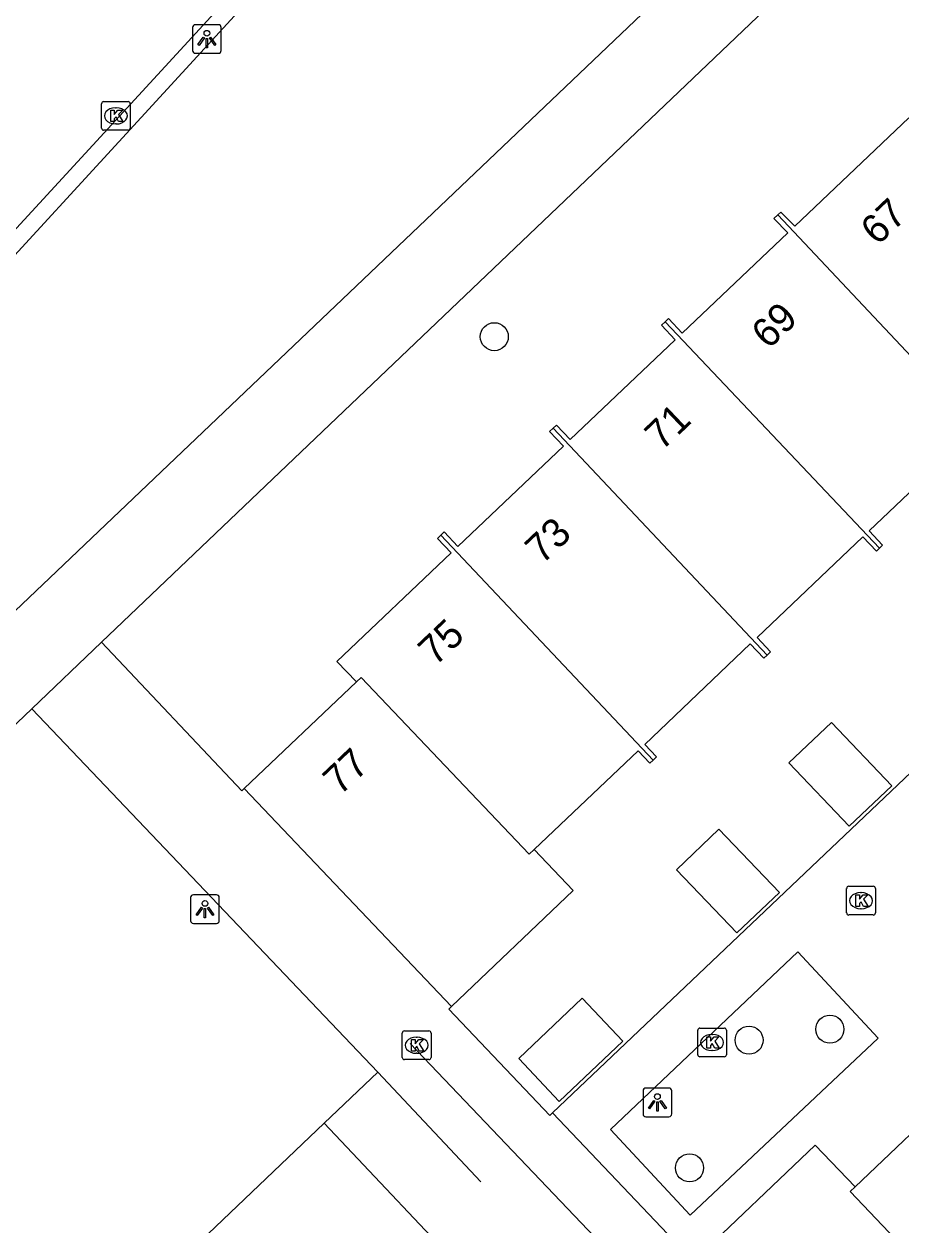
# Model space of a CAD drawing. Extents: x 162532 to 163264, y 381233 to 382042.
# Drawn here: x 163000.28 to 163030.86, y 381418.45 to 381460.32 of the extents above; entities that cross this region are included whole.
import ezdxf

# ---------------------------------------------------------------- set-up
doc = ezdxf.new("R2010")
doc.units = 0
for name, color, linetype in [('IMGEO_Boom', 7, 'Continuous'), ('IMGEO_Kolk', 7, 'Continuous'), ('IMGEO_Lichtpunt', 7, 'Continuous'), ('IMGEO_Muur', 7, 'Continuous'), ('IMGEO_Pand', 7, 'Continuous'), ('IMGEO_Pand_nummerreeks', 7, 'Continuous'), ('IMGEO_Rijbaan_lokaal_open', 7, 'Continuous'), ('IMGEO_Voetpad_gesloten', 7, 'Continuous'), ('IMGEO_Voetpad_open', 7, 'Continuous')]:
    doc.layers.add(name, color=color, linetype=linetype)

msp = doc.modelspace()

# ---------------------------------------------------------------- linework, layer by layer
at = {"layer": 'IMGEO_Boom'}
for centre in [(163016.681, 381449.417), (163028.386, 381425.275), (163025.567, 381424.892), (163023.491, 381420.44)]:
    msp.add_circle(centre, 0.489, dxfattribs=at)
at = {"layer": 'IMGEO_Kolk'}
for p, q in [((163002.984, 381456.688), (163002.984, 381457.54)), ((163003.059, 381457.614), (163003.911, 381457.614)), ((163003.985, 381457.54), (163003.985, 381456.688)), ((163003.472, 381457.394), (163003.497, 381457.394)), ((163003.495, 381456.834), (163003.47, 381456.834)), ((163003.911, 381456.614), (163003.059, 381456.614)), ((163029.045, 381430.256), (163029.897, 381430.256)), ((163028.97, 381429.33), (163028.97, 381430.182)), ((163029.458, 381430.036), (163029.483, 381430.036)), ((163029.971, 381430.182), (163029.971, 381429.33)), ((163029.481, 381429.476), (163029.456, 381429.476)), ((163029.897, 381429.256), (163029.045, 381429.256)), ((163013.549, 381425.214), (163014.401, 381425.214)), ((163023.777, 381424.386), (163023.777, 381425.238)), ((163023.852, 381425.312), (163024.704, 381425.312)), ((163024.778, 381425.238), (163024.778, 381424.386)), ((163013.474, 381424.288), (163013.474, 381425.14)), ((163013.962, 381424.994), (163013.987, 381424.994)), ((163014.475, 381425.14), (163014.475, 381424.288)), ((163024.265, 381425.092), (163024.29, 381425.092)), ((163013.985, 381424.434), (163013.96, 381424.434)), ((163024.288, 381424.532), (163024.263, 381424.532)), ((163014.401, 381424.214), (163013.549, 381424.214)), ((163024.704, 381424.312), (163023.852, 381424.312))]:
    msp.add_line(p, q, dxfattribs=at)
for points in [[(163002.984, 381456.688), (163002.984, 381457.54)], [(163003.059, 381457.614), (163003.911, 381457.614)], [(163003.985, 381457.54), (163003.985, 381456.688)], [(163003.305, 381457.314), (163003.428, 381457.314), (163003.428, 381457.163), (163003.558, 381457.314), (163003.722, 381457.314), (163003.576, 381457.163), (163003.729, 381456.914), (163003.577, 381456.914), (163003.492, 381457.078), (163003.428, 381457.011), (163003.428, 381456.914), (163003.305, 381456.914), (163003.305, 381457.314)], [(163003.911, 381456.614), (163003.059, 381456.614)], [(163029.045, 381430.256), (163029.897, 381430.256)], [(163028.97, 381429.33), (163028.97, 381430.182)], [(163029.291, 381429.956), (163029.414, 381429.956), (163029.414, 381429.805), (163029.544, 381429.956), (163029.708, 381429.956), (163029.562, 381429.805), (163029.715, 381429.556), (163029.563, 381429.556), (163029.478, 381429.72), (163029.414, 381429.653), (163029.414, 381429.556), (163029.291, 381429.556), (163029.291, 381429.956)], [(163029.971, 381430.182), (163029.971, 381429.33)], [(163029.897, 381429.256), (163029.045, 381429.256)], [(163013.549, 381425.214), (163014.401, 381425.214)], [(163023.777, 381424.386), (163023.777, 381425.238)], [(163023.852, 381425.312), (163024.704, 381425.312)], [(163024.778, 381425.238), (163024.778, 381424.386)], [(163013.474, 381424.288), (163013.474, 381425.14)], [(163013.795, 381424.914), (163013.918, 381424.914), (163013.918, 381424.763), (163014.048, 381424.914), (163014.212, 381424.914), (163014.066, 381424.763), (163014.219, 381424.514), (163014.067, 381424.514), (163013.982, 381424.678), (163013.918, 381424.611), (163013.918, 381424.514), (163013.795, 381424.514), (163013.795, 381424.914)], [(163014.475, 381425.14), (163014.475, 381424.288)], [(163024.098, 381425.012), (163024.221, 381425.012), (163024.221, 381424.861), (163024.351, 381425.012), (163024.515, 381425.012), (163024.369, 381424.861), (163024.522, 381424.612), (163024.37, 381424.612), (163024.285, 381424.776), (163024.221, 381424.709), (163024.221, 381424.612), (163024.098, 381424.612), (163024.098, 381425.012)], [(163014.401, 381424.214), (163013.549, 381424.214)], [(163024.704, 381424.312), (163023.852, 381424.312)]]:
    msp.add_lwpolyline(points, dxfattribs=at)
for centre, start, end in [((163003.061, 381457.538), 91.552, 178.448), ((163003.061, 381457.538), 91.552, 178.448), ((163003.909, 381457.538), 1.552, 88.448), ((163003.909, 381457.538), 1.552, 88.448), ((163003.061, 381456.69), 181.552, 268.448), ((163003.061, 381456.69), 181.552, 268.448), ((163003.909, 381456.69), 271.552, 358.448), ((163003.909, 381456.69), 271.552, 358.448), ((163029.047, 381430.18), 91.552, 178.448), ((163029.047, 381430.18), 91.552, 178.448), ((163029.895, 381430.18), 1.552, 88.448), ((163029.895, 381430.18), 1.552, 88.448), ((163029.047, 381429.332), 181.552, 268.448), ((163029.047, 381429.332), 181.552, 268.448), ((163029.895, 381429.332), 271.552, 358.448), ((163029.895, 381429.332), 271.552, 358.448), ((163013.551, 381425.138), 91.552, 178.448), ((163013.551, 381425.138), 91.552, 178.448), ((163014.399, 381425.138), 1.552, 88.448), ((163014.399, 381425.138), 1.552, 88.448), ((163023.854, 381425.236), 91.552, 178.448), ((163023.854, 381425.236), 91.552, 178.448), ((163024.702, 381425.236), 1.552, 88.448), ((163024.702, 381425.236), 1.552, 88.448), ((163023.854, 381424.388), 181.552, 268.448), ((163023.854, 381424.388), 181.552, 268.448), ((163024.702, 381424.388), 271.552, 358.448), ((163024.702, 381424.388), 271.552, 358.448), ((163013.551, 381424.29), 181.552, 268.448), ((163013.551, 381424.29), 181.552, 268.448), ((163014.399, 381424.29), 271.552, 358.448), ((163014.399, 381424.29), 271.552, 358.448)]:
    msp.add_arc(centre, 0.0765, start, end, dxfattribs=at)
for centre, major_axis, ratio, start_param, end_param in [((163003.471, 381457.114), (-0.387, 0.002), 0.722429, 4.712389, 7.853982), ((163003.496, 381457.114), (-0.39, 0.002), 0.717154, 1.570796, 4.712389), ((163029.457, 381429.756), (-0.387, 0.002), 0.722429, 4.712389, 7.853982), ((163029.482, 381429.756), (-0.39, 0.002), 0.717154, 1.570796, 4.712389), ((163013.961, 381424.714), (-0.387, 0.002), 0.722429, 4.712389, 7.853982), ((163013.986, 381424.714), (-0.39, 0.002), 0.717154, 1.570796, 4.712389), ((163024.264, 381424.812), (-0.387, 0.002), 0.722429, 4.712389, 7.853982), ((163024.289, 381424.812), (-0.39, 0.002), 0.717154, 1.570796, 4.712389)]:
    msp.add_ellipse(centre, major_axis=major_axis, ratio=ratio, start_param=start_param, end_param=end_param, dxfattribs=at)
at = {"layer": 'IMGEO_Lichtpunt'}
for p, q in [((163006.16, 381460.198), (163006.16, 381459.391)), ((163006.16, 381460.198), (163006.16, 381459.391)), ((163007.062, 381460.293), (163006.254, 381460.293)), ((163007.062, 381460.293), (163006.254, 381460.293)), ((163007.156, 381459.391), (163007.156, 381460.198)), ((163007.156, 381459.391), (163007.156, 381460.198)), ((163006.254, 381459.297), (163007.062, 381459.297)), ((163006.254, 381459.297), (163007.062, 381459.297)), ((163006.093, 381429.863), (163006.093, 381429.056)), ((163006.093, 381429.863), (163006.093, 381429.056)), ((163006.995, 381429.958), (163006.187, 381429.958)), ((163006.995, 381429.958), (163006.187, 381429.958)), ((163007.089, 381429.056), (163007.089, 381429.863)), ((163007.089, 381429.056), (163007.089, 381429.863)), ((163006.187, 381428.962), (163006.995, 381428.962)), ((163006.187, 381428.962), (163006.995, 381428.962)), ((163021.872, 381423.126), (163021.872, 381422.319)), ((163021.872, 381423.126), (163021.872, 381422.319)), ((163022.774, 381423.221), (163021.966, 381423.221)), ((163022.774, 381423.221), (163021.966, 381423.221)), ((163022.868, 381422.319), (163022.868, 381423.126)), ((163022.868, 381422.319), (163022.868, 381423.126)), ((163021.966, 381422.225), (163022.774, 381422.225)), ((163021.966, 381422.225), (163022.774, 381422.225))]:
    msp.add_line(p, q, dxfattribs=at)
for points in [[(163006.534, 381459.862), (163006.573, 381459.834), (163006.385, 381459.572), (163006.347, 381459.599), (163006.534, 381459.862)], [(163006.636, 381459.814), (163006.683, 381459.814), (163006.683, 381459.492), (163006.636, 381459.492), (163006.636, 381459.814)], [(163006.746, 381459.834), (163006.784, 381459.861), (163006.971, 381459.599), (163006.932, 381459.571), (163006.746, 381459.834)], [(163006.467, 381429.527), (163006.506, 381429.499), (163006.318, 381429.237), (163006.28, 381429.264), (163006.467, 381429.527)], [(163006.569, 381429.479), (163006.616, 381429.479), (163006.616, 381429.157), (163006.569, 381429.157), (163006.569, 381429.479)], [(163006.679, 381429.499), (163006.717, 381429.526), (163006.904, 381429.264), (163006.865, 381429.236), (163006.679, 381429.499)], [(163022.246, 381422.79), (163022.285, 381422.762), (163022.097, 381422.5), (163022.059, 381422.527), (163022.246, 381422.79)], [(163022.348, 381422.742), (163022.395, 381422.742), (163022.395, 381422.42), (163022.348, 381422.42), (163022.348, 381422.742)], [(163022.458, 381422.762), (163022.496, 381422.789), (163022.683, 381422.527), (163022.644, 381422.499), (163022.458, 381422.762)]]:
    msp.add_lwpolyline(points, dxfattribs=at)
for centre in [(163006.659, 381459.996), (163006.592, 381429.661), (163022.371, 381422.924)]:
    msp.add_circle(centre, 0.0994, dxfattribs=at)
for centre, start, end in [((163006.254, 381460.198), 90, 180), ((163006.254, 381460.198), 90, 180), ((163007.062, 381460.198), 0, 90), ((163007.062, 381460.198), 0, 90), ((163006.254, 381459.391), 180, 270), ((163006.254, 381459.391), 180, 270), ((163007.062, 381459.391), 270, 0), ((163007.062, 381459.391), 270, 360), ((163006.187, 381429.863), 90, 180), ((163006.187, 381429.863), 90, 180), ((163006.995, 381429.863), 0, 90), ((163006.995, 381429.863), 0, 90), ((163006.187, 381429.056), 180, 270), ((163006.187, 381429.056), 180, 270), ((163006.995, 381429.056), 270, 0), ((163006.995, 381429.056), 270, 360), ((163021.966, 381423.126), 90, 180), ((163021.966, 381423.126), 90, 180), ((163022.774, 381423.126), 0, 90), ((163022.774, 381423.126), 0, 90), ((163021.966, 381422.319), 180, 270), ((163021.966, 381422.319), 180, 270), ((163022.774, 381422.319), 270, 0), ((163022.774, 381422.319), 270, 360)]:
    msp.add_arc(centre, 0.0946, start, end, dxfattribs=at)
at = {"layer": 'IMGEO_Muur'}
for points in [[(163013.744, 381424.78), (163035.926, 381401.526)], [(163012.619, 381423.775), (163016.208, 381419.949)]]:
    msp.add_lwpolyline(points, dxfattribs=at)
at = {"layer": 'IMGEO_Pand'}
for points in [[(163026.567, 381453.662), (163026.674, 381453.762), (163027.158, 381453.268), (163031.134, 381457.046), (163031.821, 381456.333)], [(163022.639, 381449.938), (163022.759, 381450.052), (163023.236, 381449.542), (163026.916, 381453.038), (163026.429, 381453.533), (163026.567, 381453.662)], [(163026.567, 381453.662), (163034.019, 381445.755)], [(163018.733, 381446.223), (163018.853, 381446.337), (163019.328, 381445.828), (163022.995, 381449.313), (163022.518, 381449.823), (163022.639, 381449.938)], [(163030.115, 381442.042), (163022.639, 381449.938)], [(163014.82, 381442.501), (163014.939, 381442.614), (163015.412, 381442.107), (163019.09, 381445.602), (163018.612, 381446.108), (163018.733, 381446.223)], [(163026.198, 381438.317), (163018.733, 381446.223)], [(163034.019, 381445.755), (163033.901, 381445.643), (163033.429, 381446.139), (163029.753, 381442.644), (163030.224, 381442.146), (163030.115, 381442.042)], [(163011.871, 381437.382), (163011.191, 381438.096), (163015.175, 381441.882), (163014.701, 381442.387), (163014.82, 381442.501)], [(163022.223, 381434.656), (163014.82, 381442.501)], [(163030.115, 381442.042), (163030.005, 381441.938), (163029.533, 381442.434), (163025.85, 381438.932), (163026.313, 381438.426), (163026.198, 381438.317)], [(163026.198, 381438.317), (163026.083, 381438.208), (163025.61, 381438.704), (163021.926, 381435.201), (163022.339, 381434.766), (163022.223, 381434.656)], [(163007.962, 381433.668), (163011.871, 381437.382)], [(163018.07, 381431.535), (163017.897, 381431.371), (163012.036, 381437.539), (163011.871, 381437.382)], [(163028.447, 381435.971), (163030.545, 381433.758), (163029.057, 381432.347), (163026.959, 381434.56), (163028.447, 381435.971)], [(163022.223, 381434.656), (163022.107, 381434.546), (163021.694, 381434.981), (163018.07, 381431.535)], [(163015.188, 381426.061), (163007.962, 381433.668)], [(163024.513, 381432.248), (163026.628, 381430.044), (163025.137, 381428.63), (163023.031, 381430.826), (163024.513, 381432.248)], [(163018.07, 381431.535), (163019.432, 381430.105), (163015.188, 381426.061)], [(163021.162, 381424.861), (163018.946, 381422.759), (163017.532, 381424.25), (163019.748, 381426.352), (163021.162, 381424.861)], [(163029.263, 381419.775), (163032.884, 381423.218), (163032.414, 381423.713), (163032.534, 381423.826)], [(163032.936, 381398.685), (163021.271, 381387.6), (163020.957, 381387.925), (163022.321, 381389.236), (163000.793, 381411.877), (162999.447, 381410.585), (162999.122, 381410.927), (163010.747, 381421.993)], [(163010.747, 381421.993), (163016.043, 381416.399), (163014.737, 381415.163), (163026.18, 381403.213), (163027.485, 381404.447), (163032.936, 381398.685)], [(163023.629, 381417.19), (163027.876, 381421.232), (163029.263, 381419.775)], [(163034.791, 381413.286), (163034.961, 381413.448), (163029.092, 381419.613), (163029.263, 381419.775)]]:
    msp.add_lwpolyline(points, dxfattribs=at)
at = {"layer": 'IMGEO_Rijbaan_lokaal_open'}
msp.add_lwpolyline([(163008.651, 381462.597), (162983.408, 381435.155), (162981.565, 381433.154), (162977.803, 381429.072), (162977.32, 381428.547)], dxfattribs=at)
at = {"layer": 'IMGEO_Voetpad_gesloten'}
for points in [[(163046.493, 381448.74), (163018.717, 381422.363)], [(163023.515, 381418.788), (163020.734, 381421.78), (163027.264, 381427.971), (163030.073, 381424.965), (163023.515, 381418.788)], [(163023.629, 381417.19), (163018.717, 381422.363)]]:
    msp.add_lwpolyline(points, dxfattribs=at)
at = {"layer": 'IMGEO_Voetpad_open'}
for points in [[(163019.53, 381471.094), (163016.526, 381467.826), (163015.279, 381468.958), (162987.591, 381438.801), (162993.389, 381433.61), (163026.204, 381464.849)], [(163030.823, 381465.305), (163002.988, 381438.773)], [(163002.988, 381438.773), (163000.55, 381436.449)], [(163002.988, 381438.773), (163007.88, 381433.59), (163007.962, 381433.668)], [(162983.379, 381420.58), (162988.699, 381425.655), (162988.941, 381425.384), (163000.55, 381436.449)], [(163000.55, 381436.449), (163012.619, 381423.775), (163010.747, 381421.993)], [(163018.717, 381422.363), (163018.616, 381422.267), (163015.096, 381425.973), (163015.188, 381426.061)]]:
    msp.add_lwpolyline(points, dxfattribs=at)

# ---------------------------------------------------------------- texts
at = {"layer": 'IMGEO_Pand_nummerreeks'}
for s, rotation, p in [('67', 43.5391, (163030.05, 381452.568)), ('69', 43.5333, (163026.243, 381448.951)), ('71', 43.5448, (163022.524, 381445.417)), ('73', 43.5391, (163018.351, 381441.452)), ('75', 43.5391, (163014.623, 381437.909)), ('77', 43.5333, (163011.303, 381433.395))]:
    msp.add_text(s, height=1, rotation=rotation, dxfattribs=at).set_placement(p)

doc.saveas('drawing.dxf')
